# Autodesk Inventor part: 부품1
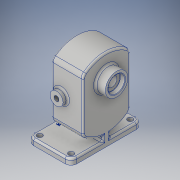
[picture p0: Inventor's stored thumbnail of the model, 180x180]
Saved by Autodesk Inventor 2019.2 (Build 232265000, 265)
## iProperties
Created: 2019-03
Part Number: 부품1
Material: 알루미늄 6061
Document SubType Name: Modeling
Designer: User
Density: 2.7 g/cm^3
Appearance: 알루미늄 - 평지
Author: User
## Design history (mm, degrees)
sketch "스케치1"
  geometry: L1 (36.5, -60)-(-36.5, -60); L2 (-36.5, -60)-(-36.5, 60); L3 (-36.5, 60)-(36.5, 60); L4 (36.5, 60)-(36.5, -60); L5 (-51.1, 0)-(51.1, 0) reference; L6 (0, -84)-(0, 84) reference; 1 further point
  constraints: 8 end point, 2 parallel, 1 horizontal, 1 perpendicular
  dimensions: "d0" = 73 distance of L1.start L1.end; "d1" = 120 distance of L1.end L2.end; "d2" = 60 distance between parallel lines of L5 L3; "d3" = 36.5 distance between parallel lines of L6 L4
extrude "돌출1" new body sketch "스케치1" distance "d4" = 10; taper "d5" = 0 deg
sketch "스케치2"
  geometry: L1 (60, 0)-(60, 78); L2 (20, 138)-(100, 138); L3 (20, 33.279)-(20, 122.721); L4 (60, -27.607)-(60, 165.644) reference; L5 (-33.471, 0)-(200.826, 0) reference; L6 (100, 138)-(100, 134.952); L7 (100, 122.721)-(100, 33.279); L8 (60, 78)-(167.355, 78); A1 r 60 centre (60, 78) between (100, 122.721) and (20, 122.721); A2 r 60 centre (60, 90.231) between (100, 134.952) and (96.306, 138); A3 r 60 centre (60, 78) between (20, 33.279) and (100, 33.279); 1 further point
  constraints: 12 end point, 7 point on circle, 3 centre point, 3 point on line, 2 horizontal, 2 parallel, 2 perpendicular, 2 symmetric about line, 1 midpoint, 1 vertical, 1 other
  dimensions: "d6" = 78 distance of L1.start L1.end; "d7" = 80 distance of L2.start L2.end; "d8" = 40 distance between parallel lines of L4 L3; "d10" = 138 distance from line of L5 point (60, 138)
extrude "돌출2" join sketch "스케치2" distance "d12" = 53; taper "d13" = 0 deg
sketch "스케치3"
  geometry: L1 (-60, 56)-(-60, 100); L2 (-84, 56)-(-84, 100); L3 (-36, 100)-(-36, 56); L4 (-100, 122.721)-(-100, 33.279) reference; L5 (-100, 78)-(99.896, 78); A1 r 24 centre (-60, 56) between (-84, 56) and (-36, 56); A2 r 24 centre (-60, 100) between (-36, 100) and (-84, 100); 2 further points
  constraints: 10 end point, 4 point on circle, 4 tangent, 2 centre point, 2 midpoint, 1 horizontal, 1 parallel, 1 vertical
  dimensions: "d14" = 24 radius of A2; "d16" = 22 distance from line of L5 L1.end; "d17" = 22 distance from line of L5 L1.start
extrude "돌출3" cut sketch "스케치3" distance "d18" = 29; taper "d19" = 0 deg
sketch "스케치4"
  geometry: C1 r 12.5 at (-60, 100); C2 r 12.5 at (-60, 56); A1 r 24 centre (-60, 100) between (-36, 100) and (-84, 100) reference; A2 r 24 centre (-60, 56) between (-84, 56) and (-36, 56) reference; 1 further point
  constraints: 2 centre point, 1 coincident, 1 concentric
  dimensions: "d20" = 25 diameter of C1; "d21" = 25 diameter of C2
extrude "돌출4" cut sketch "스케치4" distance "d22" = 15; taper "d23" = 0 deg
sketch "스케치6"
  geometry: L1 (27.5, 87.5)-(27.5, 112.5) reference; L2 (27.5, 100)-(53.189, 100); L3 (36.5, 100)-(53.5, 100); L4 (53.5, 100)-(53.5, 119); L5 (53.5, 119)-(36.5, 119); L6 (36.5, 119)-(36.5, 100); L7 (36.5, 33.279)-(36.5, 122.721) reference; 1 further point
  constraints: 10 end point, 2 horizontal, 2 parallel, 1 collinear, 1 midpoint, 1 perpendicular, 1 point on line
  dimensions: "d25" = 17 distance of L4.end L5.end; "d26" = 19 distance between parallel lines of L2 L5
revolve "회전1" sketch "스케치6" stored, may be unused: angle "d27" = 90 deg
sketch "스케치7"
  geometry: C1 r 14 at (0, 0); 1 further point
  constraints: 1 centre point
  dimensions: "d28" = 28 diameter of C1
extrude "돌출5" cut sketch "스케치7" distance "d29" = 8; taper "d30" = 0 deg
sketch "스케치8"
  geometry: C1 r 8.5 at (0, 0); 1 further point
  constraints: 1 centre point
  dimensions: "d31" = 17 diameter of C1
extrude "돌출6" cut sketch "스케치8" distance "d32" = 30; taper "d33" = 0 deg
sketch "스케치10"
  geometry: L1 (0, 0)-(78, 0); L2 (76.222, -74.323)-(76.222, 121.824); L3 (87.222, -48)-(76.222, -48); L4 (76.222, -40)-(87.222, -40); L5 (87.222, -40)-(87.222, -48); L6 (76.222, -48)-(76.222, -40); L7 (87.222, 40)-(87.222, 48); L8 (87.222, 48)-(76.222, 48); L9 (76.222, 74.323)-(76.222, -121.824); L10 (76.222, 48)-(76.222, 40)
  constraints: 20 end point, 6 symmetric about line, 4 point on line, 2 horizontal, 2 vertical, 1 parallel
  dimensions: "d34" = 78 distance of L1.start L1.end; "d35" = 8 distance of L4.end L3.start; "d36" = 11 distance between parallel lines of L5 L2
revolve "회전2" sketch "스케치10" stored, may be unused: angle "d38" = 90 deg
sketch "스케치11"
  geometry: L1 (-36.5, 10)-(36.5, 10) reference; L2 (36.5, 18)-(36.5, 33.279) reference; L3 (36.5, 10)-(36.5, 33.279); L4 (36.5, 33.279)-(24.801, 24.314); L5 (24.801, 24.314)-(-6.5, 24.314); L6 (36.5, 33.279)-(-16.5, 33.279) reference; L7 (-6.5, 24.314)-(-6.5, 10); L8 (-6.5, 10)-(36.5, 10); 1 further point
  constraints: 10 end point, 2 perpendicular, 1 collinear, 1 parallel
  dimensions: "d41" = 43 distance between parallel lines of L7 L3
extrude "돌출7" join sketch "스케치11" stored distance "d42" = 12; taper "d43" = 0 deg
sketch "스케치12"
  geometry: C1 r 11 at (0, 0) reference; 2 further points
  constraints: 1 coincident
hole "구멍1" sketch "스케치12" at (0, 0) diameter "d44" = 8.376; stored, may be unused: countersink angle "d48" = 90 deg, drill point angle "d50" = 0 deg; dims "d45" = 20, "d46" = 4, "d47" = 2, "d49" = 27.3
fillet "모깎기1" dims "d51" = 10
sketch "스케치13"
  geometry: L1 (-60, 56)-(-60, 100); L2 (-29, 56)-(-29, 100); L3 (-91, 100)-(-91, 56); C1 r 12.5 at (-60, 56) reference; C2 r 8.5 at (-60, 100) reference; A1 r 31 centre (-60, 56) between (-91, 56) and (-29, 56); A2 r 31 centre (-60, 100) between (-29, 100) and (-91, 100); A3 r 60 centre (-60, 78) between (-20, 122.721) and (-100, 122.721) reference; A4 r 60 centre (-60, 78) between (-100, 33.279) and (-20, 33.279) reference; 8 further points
  constraints: 8 end point, 6 point on circle, 4 coincident, 4 tangent, 2 centre point, 1 midpoint, 1 parallel, 1 vertical
  dimensions: "d52" = 31 radius of A2
hole "구멍2" sketch "스케치13" diameter "d54" = 4.134; stored, may be unused: countersink angle "d58" = 90 deg, drill point angle "d60" = 118 deg; dims "d55" = 10, "d56" = 4, "d57" = 2, "d59" = 12
hole "구멍3" sketch "스케치13" diameter "d61" = 4.134; stored, may be unused: countersink angle "d65" = 90 deg, drill point angle "d67" = 118 deg; dims "d62" = 10, "d63" = 4, "d64" = 2, "d66" = 12
hole "구멍4" sketch "스케치13" diameter "d68" = 4.134; stored, may be unused: countersink angle "d72" = 90 deg, drill point angle "d74" = 118 deg; dims "d69" = 10, "d70" = 4, "d71" = 2, "d73" = 12
hole "구멍5" sketch "스케치13" diameter "d75" = 4.134; stored, may be unused: countersink angle "d79" = 90 deg, drill point angle "d81" = 118 deg; dims "d76" = 10, "d77" = 4, "d78" = 2, "d80" = 12
hole "구멍6" sketch "스케치13" diameter "d82" = 4.134; stored, may be unused: countersink angle "d86" = 90 deg, drill point angle "d88" = 118 deg; dims "d83" = 10, "d84" = 4, "d85" = 2, "d87" = 12
hole "구멍7" sketch "스케치13" diameter "d89" = 4.134; stored, may be unused: countersink angle "d93" = 90 deg, drill point angle "d95" = 118 deg; dims "d90" = 10, "d91" = 4, "d92" = 2, "d94" = 12
sketch "스케치14"
  geometry: A1 r 10 centre (-26.5, -50) between (-36.5, -50) and (-26.5, -60) reference; 2 further points
  constraints: 1 coincident
hole "구멍8" sketch "스케치14" at (-26.5, -50) diameter "d96" = 9; stored, may be unused: countersink angle "d100" = 90 deg, drill point angle "d102" = 118 deg; dims "d97" = 10, "d98" = 4, "d99" = 2, "d101" = 12
sketch "스케치15"
  geometry: A1 r 10 centre (26.5, -50) between (26.5, -60) and (36.5, -50) reference; 2 further points
  constraints: 1 coincident
hole "구멍9" sketch "스케치15" at (26.5, -50) diameter "d103" = 9; stored, may be unused: countersink angle "d107" = 90 deg, drill point angle "d109" = 118 deg; dims "d104" = 10, "d105" = 4, "d106" = 2, "d108" = 12
sketch "스케치16"
  geometry: A1 r 10 centre (26.5, 50) between (36.5, 50) and (26.5, 60) reference; 2 further points
  constraints: 1 coincident
hole "구멍10" sketch "스케치16" at (26.5, 50) diameter "d110" = 9; stored, may be unused: countersink angle "d114" = 90 deg, drill point angle "d116" = 118 deg; dims "d111" = 10, "d112" = 4, "d113" = 2, "d115" = 12
sketch "스케치17"
  geometry: A1 r 10 centre (-26.5, 50) between (-26.5, 60) and (-36.5, 50) reference; 2 further points
  constraints: 1 coincident
hole "구멍11" sketch "스케치17" at (-26.5, 50) diameter "d117" = 9; stored, may be unused: countersink angle "d121" = 90 deg, drill point angle "d123" = 118 deg; dims "d118" = 10, "d119" = 4, "d120" = 2, "d122" = 12
sketch "스케치18"
  geometry: L1 (-36.5, 50)-(-36.5, -50) reference; L2 (26.5, 60)-(-26.5, 60) reference; 2 further points
  constraints: 1 other
  dimensions: "d124" = 10 distance from line of point (-26.5, 0) L1; "d125" = 60 distance from line of point (-26.5, 0) L2
feature "엠보싱1" sketch "스케치18" dims "d7" = 80, "d8" = 40, "d10" = 138, "d126" = 0.5, "d127" = 0
fillet "모깎기2" dims "d128" = 3
fillet "모깎기3" dims "d129" = 10
chamfer "모따기1" distance "d130" = 1; stored, may be unused: second distance "d131" = 2, angle "d132" = 30 deg
fillet "모깎기4" dims "d133" = 0.5
fillet "모깎기5" dims "d134" = 3
fillet "모깎기6" dims "d135" = 3
fillet "모깎기7" dims "d136" = 3
chamfer "모따기2" distance "d137" = 1; stored, may be unused: second distance "d138" = 2, angle "d139" = 30 deg
fillet "모깎기8" dims "d140" = 3
node "솔리드1"
mirror "미러1"
